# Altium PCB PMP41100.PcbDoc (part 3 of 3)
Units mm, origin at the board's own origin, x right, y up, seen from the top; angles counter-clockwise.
Board outline 49.66 x 37.36 mm, 2 copper layers (Top Layer, Bottom Layer), stack 1.016 mm thick; 100 components, 64 nets, 348 pads, 1132 vias.
Unrouted connection lines stored in the file: 60.
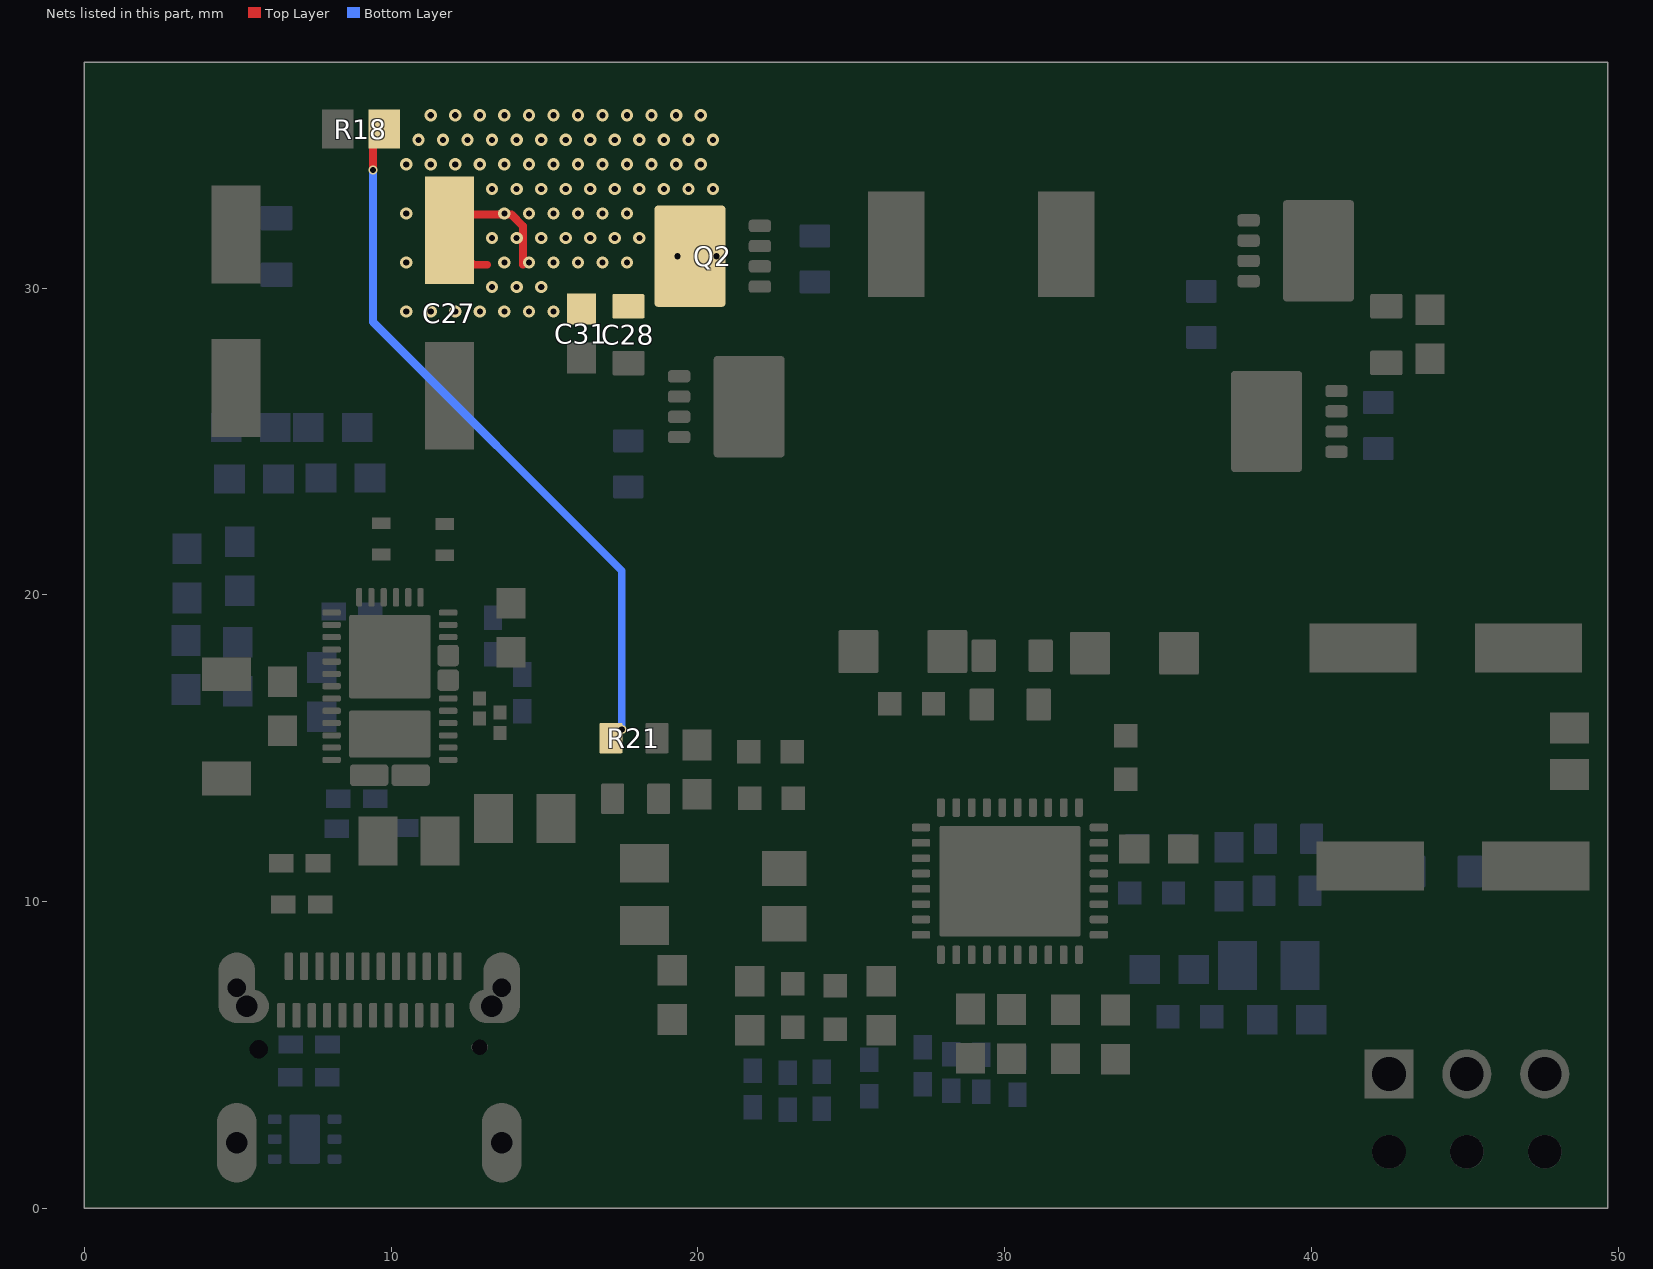
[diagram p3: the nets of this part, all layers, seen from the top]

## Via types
v1: diameter 0.4, hole 0.2, Top Layer to Bottom Layer, 988 vias
v2: diameter 0.3, hole 0.2, Top Layer to Bottom Layer, tented both sides, 103 vias
v3: diameter 0.5, hole 0.2, Top Layer to Bottom Layer, 34 vias
v4: diameter 0.4, hole 0.2, Top Layer to Bottom Layer, tented both sides, 5 vias
v5: diameter 0.4, hole 0.203, Top Layer to Bottom Layer, tented both sides, 1 vias
v6: diameter 0.61, hole 0.203, Top Layer to Bottom Layer, tented both sides, 1 vias

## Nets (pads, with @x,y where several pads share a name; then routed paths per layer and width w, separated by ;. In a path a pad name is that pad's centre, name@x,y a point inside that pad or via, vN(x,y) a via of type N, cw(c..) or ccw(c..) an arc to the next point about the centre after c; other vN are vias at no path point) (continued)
VSYS: C27.1 C28.2 C31.1 Q2.5 Q2.6 Q2.7 Q2.8 Q2.9@19.742,31.04 R18.2 R21.2 | length 29
  Top Layer w0.254: v2(9.41,33.848) 9.41,34.091 9.41,34.577 9.41,34.82 R18.2@9.774,35.185 ; C27.1@11.958,31.432 11.901,31.49 11.901,31.887 12.414,32.4 13.921,32.4 14.295,32.025 14.295,30.759 ; C27.1@12.015,31.432 12.688,30.759 13.127,30.759
  Bottom Layer w0.254: v2(9.41,33.848) 9.41,28.894 17.519,20.784 v2(17.519,15.613)
  other v1: 10.491,29.235 11.291,29.235 12.091,29.235 12.891,29.235 13.691,29.235 14.491,29.235 15.291,29.235 13.291,30.035 14.091,30.035 14.891,30.035 10.491,30.835 13.691,30.835 14.491,30.835 15.291,30.835 16.091,30.835 16.891,30.835 17.691,30.835 13.291,31.635 14.091,31.635 14.891,31.635 15.691,31.635 16.491,31.635 17.291,31.635 18.091,31.635 10.491,32.435 13.691,32.435 14.491,32.435 15.291,32.435 16.091,32.435 16.891,32.435 17.691,32.435 13.291,33.235 14.091,33.235 14.891,33.235 15.691,33.235 16.491,33.235 17.291,33.235 18.091,33.235 18.891,33.235 19.691,33.235 20.491,33.235 10.491,34.035 11.291,34.035 12.091,34.035 12.891,34.035 13.691,34.035 14.491,34.035 15.291,34.035 16.091,34.035 16.891,34.035 17.691,34.035 18.491,34.035 19.291,34.035 20.091,34.035 10.891,34.835 11.691,34.835 12.491,34.835 13.291,34.835 14.091,34.835 14.891,34.835 15.691,34.835 16.491,34.835 17.291,34.835 18.091,34.835 18.891,34.835 19.691,34.835 20.491,34.835 11.291,35.635 12.091,35.635 12.891,35.635 13.691,35.635 14.491,35.635 15.291,35.635 16.091,35.635 16.891,35.635 17.691,35.635 18.491,35.635 19.291,35.635 20.091,35.635
  other v3: 19.337,31.04 20.612,31.04
pads on no net: J1.A2 J1.A3 J1.A8 J1.A10 J1.A11 J1.ALIGN1 J1.ALIGN2 J1.B2 J1.B3 J1.B8 J1.B10 J1.B11 J2.4 J2.5 J2.6 Q1.9@39.293,29.668 Q1.9@39.293,31.218 Q1.9@39.293,32.768 Q1.9@39.878,30.648 Q1.9@39.878,31.788 Q1.9@40.028,31.218 Q2.9@19.947,31.04 Q2.9@20.097,30.47 Q2.9@20.097,31.61 Q2.9@20.682,29.49 Q2.9@20.682,31.04 Q2.9@20.682,32.59 Q3.9@38.744,25.654 Q3.9@38.894,25.084 Q3.9@38.894,26.224 Q3.9@39.479,24.104 Q3.9@39.479,25.654 Q3.9@39.479,27.204 Q4.9@20.729,24.585 Q4.9@20.729,26.135 Q4.9@20.729,27.685 Q4.9@21.314,25.565 Q4.9@21.314,26.705 Q4.9@21.464,26.135 U1.7@7.179,1.803 U1.7@7.179,2.703 U3.15 U3.16 U3.31
copper on no net: | length 1778.5
  Top Layer w0.025: 191.814,9.015 194.346,11.547 197.394,14.595 200.442,17.643 203.49,20.691 206.538,23.739 209.586,26.787 212.634,29.835 ; 191.814,10.539 192.822,11.547 195.87,14.595 198.918,17.643 201.966,20.691 205.014,23.739 208.062,26.787 211.11,29.835 ; 191.814,12.063 194.346,14.595 197.394,17.643 200.442,20.691 203.49,23.739 206.538,26.787 209.586,29.835 ; 191.814,13.587 192.822,14.595 195.87,17.643 198.918,20.691 201.966,23.739 205.014,26.787 208.062,29.835 ; 191.814,15.111 194.346,17.643 197.394,20.691 200.442,23.739 203.49,26.787 206.538,29.835 ; 191.814,16.635 192.822,17.643 195.87,20.691 198.918,23.739 201.966,26.787 205.014,29.835 ; 191.814,18.159 194.346,20.691 197.394,23.739 200.442,26.787 203.49,29.835 ; 191.814,19.683 192.822,20.691 195.87,23.739 198.918,26.787 201.966,29.835 ; 191.814,21.207 194.346,23.739 197.394,26.787 200.442,29.835 ; 191.814,22.731 192.822,23.739 195.87,26.787 198.918,29.835 ; 191.814,24.255 194.346,26.787 197.394,29.835 ; 191.814,25.779 192.822,26.787 195.87,29.835 ; 191.814,27.303 194.346,29.835 ; 191.814,28.827 192.822,29.835 ; 192.822,8.499 195.87,11.547 198.918,14.595 201.966,17.643 205.014,20.691 208.062,23.739 211.11,26.787 214.158,29.835 ; 194.346,8.499 197.394,11.547 200.442,14.595 203.49,17.643 206.538,20.691 209.586,23.739 212.634,26.787 215.682,29.835 ; 195.87,8.499 198.918,11.547 201.966,14.595 205.014,17.643 208.062,20.691 211.11,23.739 214.158,26.787 217.206,29.835 ; 197.394,8.499 200.442,11.547 203.49,14.595 206.538,17.643 209.586,20.691 212.634,23.739 215.682,26.787 218.73,29.835 ; 198.918,8.499 201.966,11.547 205.014,14.595 208.062,17.643 211.11,20.691 214.158,23.739 217.206,26.787 220.254,29.835 ; 200.442,8.499 203.49,11.547 206.538,14.595 209.586,17.643 212.634,20.691 215.682,23.739 218.73,26.787 220.254,28.311 ; 201.966,8.499 205.014,11.547 208.062,14.595 211.11,17.643 214.158,20.691 217.206,23.739 220.254,26.787 ; 203.49,8.499 206.538,11.547 209.586,14.595 212.634,17.643 215.682,20.691 218.73,23.739 220.254,25.263 ; 205.014,8.499 208.062,11.547 211.11,14.595 214.158,17.643 217.206,20.691 220.254,23.739 ; 206.538,8.499 209.586,11.547 212.634,14.595 215.682,17.643 218.73,20.691 220.254,22.215 ; 208.062,8.499 211.11,11.547 214.158,14.595 217.206,17.643 220.254,20.691 ; 209.586,8.499 212.634,11.547 215.682,14.595 218.73,17.643 220.254,19.167 ; 211.11,8.499 214.158,11.547 217.206,14.595 220.254,17.643 ; 212.634,8.499 215.682,11.547 218.73,14.595 220.254,16.119 ; 214.158,8.499 217.206,11.547 220.254,14.595 ; 215.682,8.499 218.73,11.547 220.254,13.071 ; 217.206,8.499 220.254,11.547 ; 218.73,8.499 220.254,10.023
  Top Layer w0.254: 35.142,4.853 35.142,4.878 36.796,6.533 37.209,6.533 37.38,6.704 37.38,6.891 ; 36.43,4.491 37.155,4.491 38.557,5.893 39.263,5.893 39.611,6.241 39.611,6.266
  Top Layer w0.381: 104.968,11.547 115.38,11.547 138.995,11.547 160.833,11.547 177.339,11.547 191.814,11.547 220.254,11.547 ; 104.968,14.595 115.38,14.595 138.995,14.595 160.833,14.595 177.339,14.595 191.814,14.595 220.254,14.595 ; 104.968,17.643 115.38,17.643 138.995,17.643 160.833,17.643 177.339,17.643 191.814,17.643 220.254,17.643 ; 104.968,20.691 115.38,20.691 138.995,20.691 160.833,20.691 177.339,20.691 191.814,20.691 220.254,20.691 ; 104.968,23.739 115.38,23.739 138.995,23.739 160.833,23.739 177.339,23.739 191.814,23.739 220.254,23.739 ; 104.968,26.787 115.38,26.787 138.995,26.787 160.833,26.787 177.339,26.787 191.814,26.787 220.254,26.787 ; 104.968,29.835 220.254,29.835 ; 115.38,32.883 115.38,8.499 ; 138.995,32.883 138.995,8.499 ; 160.833,32.883 160.833,8.499 ; 177.339,32.883 177.339,8.499 ; 191.814,32.883 191.814,8.499 ; 115.38,8.499 104.968,8.499 104.968,32.883 220.254,32.883 220.254,8.499 191.814,8.499 ; 115.38,8.499 138.995,8.499 ; 138.995,8.499 160.833,8.499 ; 160.833,8.499 177.339,8.499 ; 177.339,8.499 191.814,8.499

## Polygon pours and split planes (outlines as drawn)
P_OUT on Top Layer "TOP_LAYER_P_OUT_P114" (solid, remove dead copper, pour order 114): 45.771,15.557 47.665,15.549 47.664,15.107 49.251,15.098 49.251,15.557 49.251,29.722 45.771,29.722
PPHV on Top Layer "TOP_LAYER_PPHV_P111" (solid, remove dead copper, pour order 111): 0,13.27 9.884,13.27 9.911,13.298 9.911,14.383 9.861,14.433 7.183,14.433 7.009,14.607 7.009,16.213 3.581,16.213 3.581,29.774 7.845,29.774 7.845,34.462 8.817,34.51 8.809,36.711 8.344,36.711 0,36.711
BAT on Top Layer "TOP_LAYER_BAT_P115" (solid, remove dead copper, pour order 115): 45.561,-0.313 49.269,-0.313 49.269,14.688 47.673,14.694 47.673,13.85 45.561,13.852
PGND on Top Layer "TOP_LAYER_PGND_P112" (solid, remove dead copper, pour order 112): 17.021,2.146 18.344,0.823 39.088,0.823 39.088,19.175 37.976,20.286 17.021,20.286
PGND on Top Layer "TOP_LAYER_PGND_P110" (solid, remove dead copper, pour order 110): 14.439,28.533 14.439,15.718 3.751,15.718 3.751,28.533
PGND on Top Layer "TOP_LAYER_PGND_P035" (solid, pour order 35): 13.623,25.702 13.623,20.721 45.315,20.721 45.315,21.824 18.847,21.824 18.847,25.702
VBUS on Top Layer "TOP_LAYER_VBUS_P043" (solid, remove dead copper, pour order 43): 10.955,10.958 14.209,10.958 14.23,14.408 10.955,14.408
NetC1_1 on Top Layer "TOP_LAYER_NETC1_1_P008" (solid, remove dead copper, pour order 8): 7.06,3.567 7.06,12.778 11.161,12.778 11.161,3.567
PGND on Top Layer "TOP_LAYER_PGND_P040" (solid, remove dead copper, pour order 40): 16.467,0.71 16.467,21.504 14.415,21.504 14.415,9.371 11.471,9.371 11.502,3.376 6.67,3.376 6.67,0.71
SW2 on Top Layer "TOP_LAYER_SW2_P019" (solid, remove dead copper, pour order 19): 39.954,22.309 39.954,27.786 38.691,27.786 38.362,28.115 38.362,36.711 29.469,36.711 29.469,22.309
P_OUT on Top Layer "TOP_LAYER_P_OUT_P025" (solid, remove dead copper, pour order 25): 38.691,36.711 38.691,28.383 48.971,28.383 48.971,36.711
VSYS on Top Layer "TOP_LAYER_VSYS_P013" (solid, remove dead copper, pour order 13): 21.14,36.711 21.14,28.646 10.282,28.646 10.282,34.514 9.196,34.514 9.196,36.711 9.803,36.711
SW1 on Top Layer "TOP_LAYER_SW1_P018" (solid, remove dead copper, pour order 18): 19.934,28.287 19.934,22.332 28.147,22.332 28.147,36.711 21.364,36.711 21.364,28.287
PGND on Top Layer "TOP_LAYER_PGND_P026" (solid, remove dead copper, pour order 26): 39.785,0.757 45.315,0.757 45.315,28.136 39.785,28.136
PGND on Top Layer "TOP_LAYER_PGND_P007" (solid, remove dead copper, pour order 7): 0,0.34 6.996,0.34 6.996,12.778 0,12.778
PGND on Top Layer "TOP_LAYER_PGND_P032" (solid, remove dead copper, pour order 32): 13.474,28.383 13.474,20.721 19.759,20.721 19.759,28.383
DRAIN on Bottom Layer "BOTTOM_LAYER_DRAIN_P132" (solid, remove dead copper, pour order 132): 7.801,16.345 7.801,13.814 11.693,13.814 11.693,16.345 7.831,16.345
PGND on Bottom Layer "BOTTOM_LAYER_PGND_P127" (solid, remove dead copper, pour order 127): 14.89,30.753 14.89,8.707 3.77,8.707 3.77,30.753
BAT on Bottom Layer "BOTTOM_LAYER_BAT_P131" (solid, remove dead copper, pour order 131): 45.58,-0.426 49.059,-0.426 49.059,13.74 45.58,13.74
P_OUT on Bottom Layer "BOTTOM_LAYER_P_OUT_P130" (solid, remove dead copper, pour order 130): 45.79,15.557 49.269,15.557 49.269,29.609 45.79,29.609
PGND on Bottom Layer "BOTTOM_LAYER_PGND_P129" (solid, remove dead copper, pour order 129): 17.04,2.033 18.363,0.71 39.106,0.71 39.106,19.044 37.977,20.174 17.04,20.174
PPHV on Bottom Layer "BOTTOM_LAYER_PPHV_P128" (solid, remove dead copper, pour order 128): 0.019,13.158 9.771,13.158 9.93,13.316 9.93,14.271 9.88,14.321 7.201,14.321 7.028,14.494 7.028,16.101 3.6,16.101 3.6,31.04 7.864,31.04 7.864,34.349 8.835,34.398 8.827,36.598 8.363,36.598 0.019,36.598
PGND on Bottom Layer "BOTTOM_LAYER_PGND_P125" (solid, remove dead copper, pour order 125): 16.403,0.71 16.467,9.323 16.467,21.392 14.434,21.392 14.434,9.259 11.49,9.259 11.521,3.263 6.689,3.263 6.689,0.71
PGND on Bottom Layer "BOTTOM_LAYER_PGND_P124" (solid, pour order 124): 13.641,25.589 13.641,20.401 45.333,20.401 45.333,21.711 18.865,21.711 18.865,25.589
PGND on Bottom Layer "BOTTOM_LAYER_PGND_P123" (solid, remove dead copper, pour order 123): 10.841,28.271 10.841,20.9 19.778,20.9 19.778,28.271
PGND on Bottom Layer "BOTTOM_LAYER_PGND_P122" (solid, remove dead copper, pour order 122): 39.804,0.644 45.333,0.644 45.333,28.023 39.804,28.023
P_OUT on Bottom Layer "BOTTOM_LAYER_P_OUT_P121" (solid, remove dead copper, pour order 121): 38.71,36.598 38.71,28.271 48.99,28.271 48.99,36.598
SW2 on Bottom Layer "BOTTOM_LAYER_SW2_P120" (solid, remove dead copper, pour order 120): 39.973,22.196 39.973,27.673 38.71,27.673 38.381,28.003 38.381,36.598 29.469,36.598 29.469,22.196
SW1 on Bottom Layer "BOTTOM_LAYER_SW1_P119" (solid, remove dead copper, pour order 119): 19.953,28.174 19.953,22.219 28.147,22.219 28.147,36.598 21.382,36.598 21.382,28.174
VSYS on Bottom Layer "BOTTOM_LAYER_VSYS_P118" (solid, remove dead copper, pour order 118): 21.158,36.598 21.158,28.533 10.099,28.533 10.099,34.401 9.215,34.401 9.215,36.598 9.821,36.598
NetC1_1 on Bottom Layer "BOTTOM_LAYER_NETC1_1_P117" (solid, remove dead copper, pour order 117): 7.079,3.454 7.079,12.665 11.18,12.665 11.18,3.454
PGND on Bottom Layer "BOTTOM_LAYER_PGND_P116" (solid, remove dead copper, pour order 116): 0.019,0.227 7.015,0.227 7.015,12.665 0.019,12.665
NetC1_1 on Bottom Layer "BOTTOM_LAYER_NETC1_1_P000" (solid, remove dead copper, pour order 0): 6.983,1.106 10.484,1.106 10.484,5.656 6.983,5.656

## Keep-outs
Keep-Out Layer:
  text ".Layer_Name" at -9.924,-55.867 h0.3

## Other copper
Top Layer:
  text "Layer" at 106.746,30.597 h1.52
  text "Name" at 117.158,30.597 h1.52
  text "Material" at 140.773,30.597 h1.52
  text "Thickness" at 162.611,30.597 h1.52
  text "Constant" at 179.117,30.597 h1.52
  text "Board Layer Stack" at 193.592,30.597 h1.52
  text "Top Overlay" at 117.158,27.549 h1.52
  text "Top Solder" at 117.158,24.501 h1.52
  text "Solder Resist" at 140.773,24.501 h1.52
  text "0.010mm" at 162.611,24.501 h1.52
  text "3.5" at 179.117,24.501 h1.52
  text "1" at 106.746,21.453 h1.52
  text "Top Layer" at 117.158,21.453 h1.52
  text "0.036mm" at 162.611,21.453 h1.52
  text "Dielectric1" at 117.158,18.405 h1.52
  text "FR-4 High Tg" at 140.773,18.405 h1.52
  text "0.945mm" at 162.611,18.405 h1.52
  text "4.8" at 179.117,18.405 h1.52
  text "2" at 106.746,15.357 h1.52
  text "Bottom Layer" at 117.158,15.357 h1.52
  text "0.036mm" at 162.611,15.357 h1.52
  text "Bottom Solder" at 117.158,12.309 h1.52
  text "Solder Resist" at 140.773,12.309 h1.52
  text "0.010mm" at 162.611,12.309 h1.52
  text "3.5" at 179.117,12.309 h1.52
  text "Bottom Overlay" at 117.158,9.261 h1.52
  text "Total board thickness:" at 106.746,6.213 h1.52
  text "1.036mm" at 162.611,6.213 h1.52
  text ".Layer_Name" at -9.924,-55.867 h0.3
Bottom Layer:
  text ".Layer_Name" at -9.924,-55.867 h0.3

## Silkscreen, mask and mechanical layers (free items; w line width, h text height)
Top Overlay:
  text "TPS25730+BQ25756" at 40.3,35.255 h0.5
  text ".Layer_Name" at -9.924,-55.867 h0.3
Bottom Overlay:
  text ".Layer_Name" at -9.924,-55.867 h0.3
Top Paste:
  text ".Layer_Name" at -9.924,-55.867 h0.3
Bottom Paste:
  text ".Layer_Name" at -9.924,-55.867 h0.3
Top Solder:
  text ".Layer_Name" at -9.924,-55.867 h0.3
  text ".Layer_Name" at -9.924,-55.867 h0.3
Bottom Solder:
  text ".Layer_Name" at -9.924,-55.867 h0.3
Drill Guide:
  text ".Layer_Name" at -9.924,-55.867 h0.3
M1 Board Outline:
  the board outline again, w0.254
  text ".Layer_Name" at -9.924,-55.867 h0.3
M2 Board Dimensions:
  rectangle: -21.405,-44.221 -11.88,-41.046
  rectangle: -24.58,-41.046 -21.405,-37.871
  lines w0.178: -24.58,-41.046 0.82,-41.046 ; -21.405,-44.221 -21.405,-37.871 ; -18.23,-44.221 -18.23,-37.871 ; -11.88,-44.221 -11.88,-37.871 ; -5.53,-44.221 -5.53,-37.871 ; -24.58,-44.221 -24.58,-37.871 0.82,-37.871 0.82,-44.221 -24.58,-44.221
  text ".Layer_Name" at -9.924,-55.867 h0.3
M3 3D STEP Top:
  text ".Layer_Name" at -9.924,-55.867 h0.3
M4 3D STEP Bottom:
  text ".Layer_Name" at -9.924,-55.867 h0.3
Top M5 Assembly Top/M6 Assembly Bottom:
  lines w0.254: -31.996,-57.688 135.644,-57.688 ; -31.996,-52.523 135.694,-52.523 ; -31.996,-47.358 -31.996,-62.852 69.731,-62.852 135.694,-62.852 135.694,-47.358 -31.984,-47.358 -31.984,-62.852 8.034,-62.852 ; 30.615,-62.852 30.615,-47.358 ; 62.796,-52.523 62.796,-47.358 ; 84.132,-52.523 84.132,-47.358 ; 99.931,-63.017 99.931,-57.865
  text "COMPONENTS MARKED 'DNP' SHOULD NOT BE POPULATED." at 4.719,-42.151 h0.3
  text "ASSEMBLY VARIANT:" at 4.707,-45.085 h0.3
  text ".VariantName" at 31.021,-45.085 h0.3
  text "PCB VIEWED FROM TOP SIDE" at -30.383,-50.715 h0.3
  text "BOARD #:" at 32.52,-50.715 h0.3
  text ".PRJ_Number" at 46.375,-50.715 h0.3
  text "REV:" at 67.826,-50.715 h0.3
  text ".PCB_Rev" at 75.23,-50.715 h0.3
  text "SVN REV:" at 89.111,-50.715 h0.3
  text ".VersionControl_RevNumber" at 101.963,-50.715 h0.3
  text "PLOT NAME =" at -30.383,-61.096 h0.3
  text ".plot_File_Name" at -9.924,-61.096 h0.3
  text "GENERATED    :" at 32.57,-61.096 h0.3
  text ".Print_Date" at 54.656,-61.096 h0.3
  text ".Print_Time" at 73.172,-61.096 h0.3
  text "TEXAS INSTRUMENTS" at 105.291,-61.096 h0.3
Bottom M5 Assembly Top/M6 Assembly Bottom:
  lines w0.254: -32.009,-52.536 135.682,-52.536 ; -31.958,-57.7 135.682,-57.7 ; 3.754,-63.03 3.754,-57.878 ; 19.553,-52.536 19.553,-47.371 ; 40.889,-52.536 40.889,-47.371 ; 73.071,-62.865 73.071,-47.371 ; 95.651,-62.865 135.669,-62.865 135.669,-47.371 -32.009,-47.371 -32.009,-62.865 33.955,-62.865 135.682,-62.865 135.682,-47.371
  text "COMPONENTS MARKED 'DNP' SHOULD NOT BE POPULATED." at 130.411,-42.139 h0.3
  text ".VariantName" at 103.894,-45.085 h0.3
  text "ASSEMBLY VARIANT:" at 130.284,-45.085 h0.3
  text ".VersionControl_RevNumber" at 1.722,-50.728 h0.3
  text "SVN REV:" at 14.575,-50.728 h0.3
  text ".PCB_Rev" at 28.456,-50.728 h0.3
  text "REV:" at 35.86,-50.728 h0.3
  text ".PRJ_Number" at 57.31,-50.728 h0.3
  text "BOARD #:" at 71.166,-50.728 h0.3
  text "PCB VIEWED FROM BOTTOM SIDE" at 134.069,-50.728 h0.3
  text "TEXAS INSTRUMENTS" at -1.605,-61.108 h0.3
  text ".Print_Time" at 30.513,-61.108 h0.3
  text ".Print_Date" at 49.03,-61.108 h0.3
  text "GENERATED    :" at 71.115,-61.108 h0.3
  text ".plot_File_Name" at 113.609,-61.108 h0.3
  text "PLOT NAME =" at 134.069,-61.108 h0.3
M9 Title Sheet:
  drawing of 63 lines, arcs and shapes, not listed
  text "1" at 10.714,432.689 h0.3
  text "2" at 112.187,432.689 h0.3
  text "3" at 213.66,432.689 h0.3
  text "4" at 315.285,432.689 h0.3
  text "5" at 416.843,432.689 h0.3
  text "6" at 518.401,432.689 h0.3
  text "7" at 620.043,432.689 h0.3
  text "8" at 721.516,432.689 h0.3
  text "A" at -36.454,371.78 h0.3
  text "A" at 768.726,371.78 h0.3
  text "B" at -36.454,244.78 h0.3
  text "B" at 768.726,244.78 h0.3
  text "C" at -36.454,117.78 h0.3
  text "C" at 768.726,117.78 h0.3
  text "D" at -36.454,-9.22 h0.3
  text "D" at 768.726,-9.22 h0.3
  text "PROJECT TITLE:" at 690.367,-27.239 h0.3
  text ".PRJ_Title" at 691.637,-30.625 h0.3
  text "DESIGNED FOR:" at 690.367,-34.884 h0.3
  text ".PRJ_Customer" at 691.637,-38.44 h0.3
  text "FILE NAME:" at 690.367,-42.504 h0.3
  text ".PCB_File_Name_No_Path" at 691.637,-45.552 h0.3
  text "Texas Instruments (TI) and/or its licensors do not warrant the accuracy or completeness of this specification" at 564.142,-49.663 h0.3
  text "ENGINEER:" at 690.367,-49.87 h0.3
  text "LAYOUT BY:" at 728.594,-49.87 h0.3
  text "or any information contained therein. TI and/or its licensors do not warrant that this design will meet" at 562.999,-52.525 h0.3
  text ".PRJ_Engineer" at 691.637,-53.807 h0.3
  text ".PCB_Layout" at 729.877,-53.807 h0.3
  text "the specifications, will be suitable for your application or fit for any particular purpose, or will operate in" at 562.999,-55.386 h0.3
  text ".Layer_Name" at -9.924,-55.867 h0.3
  text "ALTIUM DESIGNER VERSION:" at 728.594,-57.744 h0.3
  text "an implementation. TI and/or its licensors do not warrant that the design is production worthy. You should" at 562.999,-58.248 h0.3
  text "completely validate and test your design implementation to confirm the system functionality for your application." at 564.142,-61.11 h0.3
  text ".print_Scale" at 691.637,-61.131 h0.3
  text ".Application_BuildNumber" at 729.877,-61.131 h0.3
  text "1" at 10.714,-67.564 h0.3
  text "2" at 112.187,-67.564 h0.3
  text "3" at 213.66,-67.564 h0.3
  text "4" at 315.285,-67.564 h0.3
  text "5" at 416.843,-67.564 h0.3
  text "6" at 518.401,-67.564 h0.3
  text "7" at 620.043,-67.564 h0.3
  text "8" at 721.516,-67.564 h0.3
M10 Fab Notes:
  drawing of 189 lines, arcs and shapes, not listed
  text "DESIGN INFORMATION" at 716.796,127.614 h0.3
  text "MIN. TRACK WIDTH:" at 700.424,124.258 h0.3
  text "8" at 728.269,124.258 h0.3
  text "MIL" at 732.2,124.258 h0.3
  text "MIN. CLEARANCE:" at 700.424,121.105 h0.3
  text "7.874" at 723.92,121.105 h0.3
  text "MIL" at 732.2,121.105 h0.3
  text "MIN. VIA PAD SIZE:" at 700.424,117.952 h0.3
  text "24" at 727.507,117.952 h0.3
  text "MIL" at 732.2,117.952 h0.3
  text "0.05mm (2MIL)" at 718.077,114.653 h0.3
  text "MINIMUM ANNULAR RING" at 692.062,114.444 h0.3
  text "EXTERNAL" at 736.06,114.444 h0.3
  text "PER" at 697.142,111.647 h0.3
  text "IPC-D-275 CLASS 2 LEVEL C" at 702.73,111.647 h0.3
  text "MIL, HOLES" at 740.531,109.095 h0.3
  text "+/-" at 730.562,108.877 h0.3
  text "+/-" at 752.254,108.877 h0.3
  text "REGISTRATION TOLERANCES:" at 692.062,108.85 h0.3
  text "METAL" at 722.536,108.85 h0.3
  text "5" at 737.172,108.85 h0.3
  text "3" at 758.33,108.85 h0.3
  text "MIL" at 761.283,108.85 h0.3
  text "HOLE SIZE TOLERANCE (UNLESS OTHERWISE SPECIFIED):" at 692.062,106.352 h0.3
  text "+/-" at 752.254,106.279 h0.3
  text "3" at 758.33,106.253 h0.3
  text "MIL" at 761.283,106.252 h0.3
  text "MATERIAL:" at 690.163,102.756 h0.3
  text "FR-4 High Tg" at 715.218,99.492 h0.3
  text "X" at 711.55,99.289 h0.3
  text "FR-4" at 700.856,99.174 h0.3
  text "OTHER" at 738.651,99.174 h0.3
  text "62 MIL (1.6mm) +/-10%" at 708.987,95.541 h0.3
  text "X" at 705.936,95.479 h0.3
  text "THICKNESS:" at 692.062,95.332 h0.3
  text "OTHER" at 741.623,95.332 h0.3
  text "TOLERANCE:" at 692.062,91.819 h0.3
  text "X" at 713.607,91.819 h0.3
  text "ANSI IPC-6012 TYPE 3 CLASS 2" at 718.129,91.819 h0.3
  text "OTHER +/-" at 718.128,88.157 h0.3
  text "BOW & TWIST:" at 692.062,84.469 h0.3
  text "X" at 713.607,84.469 h0.3
  text "ANSI IPC-6012 TYPE 3 CLASS 2" at 718.129,84.469 h0.3
  text "OTHER +/-" at 718.128,80.743 h0.3
  text "DRILLING:" at 690.163,77.425 h0.3
  text "NC_DRILL FILES" at 734.892,74.753 h0.3
  text "REFERENCE:" at 692.062,74.653 h0.3
  text "X" at 708.756,74.651 h0.3
  text "AS SHOWN" at 713.277,74.653 h0.3
  text "X" at 731.641,74.653 h0.3
  text "OTHER" at 742.461,71.04 h0.3
  text "PTH COPPER THICKNESS:" at 692.054,70.95 h0.3
  text "X" at 720.99,70.95 h0.3
  text "20-30 um" at 724.241,70.95 h0.3
  text "BOARD FINISH:" at 690.163,67.201 h0.3
  text "SILKSCREEN:" at 694.105,64.404 h0.3
  text "X" at 718.433,64.404 h0.3
  text "TOP" at 721.405,64.404 h0.3
  text "X" at 731.387,64.404 h0.3
  text "BOTTOM" at 734.384,64.404 h0.3
  text "SILKSCREEN COLOR:" at 694.105,60.462 h0.3
  text "X" at 718.408,60.462 h0.3
  text "WHITE" at 721.405,60.462 h0.3
  text "OTHER" at 734.384,60.462 h0.3
  text "X" at 721.735,56.819 h0.3
  text "GREEN" at 724.732,56.819 h0.3
  text "OTHER" at 740.429,56.819 h0.3
  text "SOLDER RESIST COLOR:" at 694.105,56.644 h0.3
  text "X" at 721.735,52.901 h0.3
  text "MATTE" at 724.732,52.901 h0.3
  text "SEMI-GLOSS" at 740.418,52.885 h0.3
  text "IMMERSION GOLD (ENIG)" at 717.112,48.512 h0.3
  text "ENEPIG" at 751.086,48.329 h0.3
  text "SURFACE FINISH:" at 690.163,48.304 h0.3
  text "X" at 712.591,48.304 h0.3
  text "IMM. TIN/SILVER OR EQUIV" at 698.533,44.816 h0.3
  text "OTHER" at 734.892,44.716 h0.3
  text "ARRAY/PANEL:" at 690.163,40.769 h0.3
  text "CUT AND TRIM PER M1 BOARD OUTLINE" at 717.112,40.56 h0.3
  text "N.C. ROUTE" at 717.112,37.107 h0.3
  text "X" at 734.587,37.107 h0.3
  text "V. SCORE" at 739.108,37.107 h0.3
  text "CERTIFICATION:" at 690.163,33.827 h0.3
  text "MATERIALS AND WORKMANSHIP FOR ALL PCBS" at 708.578,33.827 h0.3
  text "TO MEET OR EXCEED THE REQUIREMENTS OF:" at 708.578,31.438 h0.3
  text "X" at 699.37,28.171 h0.3
  text "ANSI IPC-A-600F CLASS ->" at 702.621,28.171 h0.3
  text "X" at 744.481,28.171 h0.3
  text "2" at 747.275,28.171 h0.3
  text "1" at 739.274,28.133 h0.3
  text "3" at 756.266,28.133 h0.3
  text "X" at 719.995,24.419 h0.3
  text "RoHS" at 723.246,24.419 h0.3
  text "OTHER" at 739.614,24.419 h0.3
  text "PER ORDER" at 749.699,24.419 h0.3
  text "ALL BOARDS MUST MEET OR EXCEED UL94-V0 REQUIREMENTS." at 690.862,20.512 h0.3
  text "PCB MUST BEAR THE UL94V-0 UL REGISTERED MATERIAL ID NUMBER" at 690.862,17.564 h0.3
  text "ADDITIONAL REQUIREMENTS:" at 690.163,13.261 h0.3
  text "MICROSECTION:" at 692.062,10.54 h0.3
  text "YES" at 715.067,10.54 h0.3
  text "REQUIRED" at 736.949,6.874 h0.3
  text "BARE BOARD ELEC. TEST:" at 692.062,6.801 h0.3
  text "NONE" at 725.227,6.801 h0.3
  text "X" at 733.952,6.801 h0.3
  text "PER ORDER" at 751.986,6.801 h0.3
  text "XX MIL VIAS REQUIRE NON-CONDUCTIVE FILL AND PLANARIZE" at 696.333,1.596 h0.3
  text "XX MIL VIAS REQUIRE CONDUCTIVE FILL AND PLANARIZE" at 696.536,-1.045 h0.3
  text "OUTER XX MIL TRACES REQUIRE 50 OHM SINGLE-ENDED IMPEDANCE" at 696.511,-5.195 h0.3
  text "LAYER 2 & 3 (INNER LAYERS) XX MIL WIDE, XX MIL SPACE / TRACES REQUIRE 100 OHM DIFFERENTIAL IMPEDANCE" at 696.308,-11.182 h0.3
  text ".Layer_Name" at -9.924,-55.867 h0.3
M11 Gerber Information:
  lines w0.254: -31.996,-57.688 135.644,-57.688 ; -31.996,-52.523 135.694,-52.523 ; -31.996,-47.358 -31.996,-62.852 69.731,-62.852 135.694,-62.852 135.694,-47.358 -31.984,-47.358 -31.984,-62.852 8.034,-62.852 ; 30.615,-62.852 30.615,-47.358 ; 62.796,-52.523 62.796,-47.358 ; 84.132,-52.523 84.132,-47.358 ; 99.931,-63.017 99.931,-57.865
  text "ALL ARTWORK VIEWED FROM TOP SIDE" at -30.383,-50.715 h0.3
  text "BOARD #:" at 32.52,-50.715 h0.3
  text ".PRJ_Number" at 46.375,-50.715 h0.3
  text "REV:" at 67.826,-50.715 h0.3
  text ".PCB_Rev" at 75.23,-50.715 h0.3
  text "SVN REV:" at 89.111,-50.715 h0.3
  text ".VersionControl_RevNumber" at 101.963,-50.715 h0.3
  text "LAYER NAME =" at -30.383,-55.867 h0.3
  text "PLOT NAME =" at -30.383,-61.096 h0.3
  text ".plot_File_Name" at -9.924,-61.096 h0.3
  text "GENERATED    :" at 32.57,-61.096 h0.3
  text ".Print_Date" at 54.656,-61.096 h0.3
  text ".Print_Time" at 73.172,-61.096 h0.3
  text "TEXAS INSTRUMENTS" at 105.291,-61.096 h0.3
M12 Stackup:
  drawing of 205 lines, arcs and shapes, not listed
  text "Layer" at 648.665,425.298 h0.3
  text "Name" at 651.122,425.298 h0.3
  text "Material" at 656.179,425.298 h0.3
  text "Thickness" at 660.886,425.298 h0.3
  text "Constant" at 664.543,425.298 h0.3
  text "Board Layer Stack" at 667.801,425.298 h0.3
  text "Top Overlay" at 651.122,424.698 h0.3
  text "Top Solder" at 651.122,424.098 h0.3
  text "Solder Resist" at 656.179,424.098 h0.3
  text "0.40mil" at 660.886,424.098 h0.3
  text "3.5" at 664.543,424.098 h0.3
  text "1" at 648.665,423.498 h0.3
  text "Top Layer" at 651.122,423.498 h0.3
  text "1.40mil" at 660.886,423.498 h0.3
  text "Dielectric1" at 651.122,422.898 h0.3
  text "FR-4 High Tg" at 656.179,422.898 h0.3
  text "37.20mil" at 660.886,422.898 h0.3
  text "4.8" at 664.543,422.898 h0.3
  text "2" at 648.665,422.298 h0.3
  text "Bottom Layer" at 651.122,422.298 h0.3
  text "1.40mil" at 660.886,422.298 h0.3
  text "Bottom Solder" at 651.122,421.698 h0.3
  text "Solder Resist" at 656.179,421.698 h0.3
  text "0.40mil" at 660.886,421.698 h0.3
  text "3.5" at 664.543,421.698 h0.3
  text "Bottom Overlay" at 651.122,421.098 h0.3
  text ".Layer_Name" at -9.924,-55.867 h0.3
M13 Component Bodies Top:
  text ".Layer_Name" at -9.924,-55.867 h0.3
M14 Component Bodies Bottom:
  text ".Layer_Name" at -9.924,-55.867 h0.3
M15 Courtyards Top:
  text ".Layer_Name" at -9.924,-55.867 h0.3
M16 Courtyards Bottom:
  text ".Layer_Name" at -9.924,-55.867 h0.3
Drill Drawing:
  circle w0.254: c3.676,81.121 r0.702
  circle w0.254: c3.676,77.963 r0.421
  circle w0.254: c3.676,77.963 r0.702
  lines w0.254: 2.974,83.577 2.974,83.928 3.325,84.279 2.974,84.63 2.974,84.98 3.325,84.98 3.676,84.63 4.027,84.98 4.378,84.98 4.378,84.63 4.027,84.279 4.378,83.928 4.378,83.577 4.027,83.577 3.676,83.928 3.325,83.577 2.974,83.577 ; 2.974,87.086 3.325,87.086 3.676,86.735 4.027,87.086 4.378,87.086 4.027,87.436 4.378,87.787 4.027,87.787 3.676,88.138 3.325,87.787 2.974,87.787 3.325,87.436 2.974,87.086 ; 2.974,91.296 4.378,91.296 3.676,89.892 2.974,91.296 ; 2.974,93.05 3.676,93.401 4.378,93.05 4.027,93.752 4.378,94.454 3.676,94.103 2.974,94.454 3.325,93.752 2.974,93.05 ; 2.974,96.559 3.325,96.559 3.325,96.208 4.027,96.208 4.027,96.559 4.378,96.559 4.378,97.261 4.027,97.261 4.027,97.611 3.325,97.611 3.325,97.261 2.974,97.261 2.974,96.559 ; 2.974,99.366 4.378,99.366 4.378,100.769 2.974,100.769 2.974,99.366 ; 2.974,103.225 3.676,102.523 4.378,103.225 3.676,103.927 2.974,103.225
  lines w0.305: 1.702,76.314 81.818,76.314 ; 1.702,104.734 81.818,104.734 ; 10.283,73.157 10.283,107.892 ; 18.647,73.157 18.647,107.892 ; 32.922,73.157 32.922,107.892 ; 39.504,73.157 39.504,107.892 ; 49.033,73.157 49.033,107.892 ; 67.431,73.157 67.431,107.892 ; 1.702,73.157 81.818,73.157 81.818,107.892 1.702,107.892 1.702,73.157
  text "Symbol" at 3.596,105.681 h1.83
  text "Count" at 11.231,105.681 h1.83
  text "Hole Size" at 19.595,105.681 h1.83
  text "Plated" at 33.869,105.681 h1.83
  text "Hole Type" at 40.451,105.681 h1.83
  text "Drill Layer Pair" at 49.98,105.681 h1.83
  text "Hole Tolerance" at 68.378,105.681 h1.83
  text "1130" at 11.231,102.523 h1.52
  text "0.200mm (7.87mil)" at 19.595,102.523 h1.52
  text "PTH" at 33.869,102.523 h1.52
  text "Round" at 40.451,102.523 h1.52
  text "Top Layer - Bottom Layer" at 49.98,102.523 h1.52
  text "2" at 11.231,99.366 h1.52
  text "0.203mm (8.00mil)" at 19.595,99.366 h1.52
  text "PTH" at 33.869,99.366 h1.52
  text "Round" at 40.451,99.366 h1.52
  text "Top Layer - Bottom Layer" at 49.98,99.366 h1.52
  text "1" at 11.231,96.208 h1.52
  text "0.500mm (19.69mil)" at 19.595,96.208 h1.52
  text "NPTH" at 33.869,96.208 h1.52
  text "Slot" at 40.451,96.208 h1.52
  text "Top Layer - Bottom Layer" at 49.98,96.208 h1.52
  text "+/-0.030mm" at 68.378,96.208 h1.52
  text "1" at 11.231,93.05 h1.52
  text "0.600mm (23.62mil)" at 19.595,93.05 h1.52
  text "NPTH" at 33.869,93.05 h1.52
  text "Round" at 40.451,93.05 h1.52
  text "Top Layer - Bottom Layer" at 49.98,93.05 h1.52
  text "+/-0.030mm" at 68.378,93.05 h1.52
  text "2" at 11.231,89.892 h1.52
  text "0.600mm (23.62mil)" at 19.595,89.892 h1.52
  text "PTH" at 33.869,89.892 h1.52
  text "Slot" at 40.451,89.892 h1.52
  text "Top Layer - Bottom Layer" at 49.98,89.892 h1.52
  text "+/-0.050mm" at 68.378,89.892 h1.52
  text "2" at 11.231,86.735 h1.52
  text "0.700mm (27.56mil)" at 19.595,86.735 h1.52
  text "PTH" at 33.869,86.735 h1.52
  text "Slot" at 40.451,86.735 h1.52
  text "Top Layer - Bottom Layer" at 49.98,86.735 h1.52
  text "+/-0.050mm" at 68.378,86.735 h1.52
  text "2" at 11.231,83.577 h1.52
  text "0.700mm (27.56mil)" at 19.595,83.577 h1.52
  text "PTH" at 33.869,83.577 h1.52
  text "Slot" at 40.451,83.577 h1.52
  text "Top Layer - Bottom Layer" at 49.98,83.577 h1.52
  text "+/-0.050mm" at 68.378,83.577 h1.52
  text "3" at 11.231,80.419 h1.52
  text "1.100mm (43.31mil)" at 19.595,80.419 h1.52
  text "NPTH" at 33.869,80.419 h1.52
  text "Round" at 40.451,80.419 h1.52
  text "Top Layer - Bottom Layer" at 49.98,80.419 h1.52
  text "3" at 11.231,77.262 h1.52
  text "1.100mm (43.31mil)" at 19.595,77.262 h1.52
  text "PTH" at 33.869,77.262 h1.52
  text "Round" at 40.451,77.262 h1.52
  text "Top Layer - Bottom Layer" at 49.98,77.262 h1.52
  text "1146 Total" at 11.231,74.104 h1.52
  text "Slot definitions :" at 3.596,71.893 h1.52
  text "Routed Path Length" at 15.045,71.893 h1.52
  text "= Calculated from tool start centre position to tool end centre position." at 28.754,71.893 h1.52
  text "Hole Length" at 15.045,70.63 h1.52
  text "= Routed Path Length + Tool Size = Slot length as defined in the PCB layout" at 23.679,70.63 h1.52
  text ".Layer_Name" at -9.924,-55.867 h0.3
M17 Embedded Cavity:
  text ".Layer_Name" at -9.924,-55.867 h0.3
M18 Embedded Assembly:
  text ".Layer_Name" at -9.924,-55.867 h0.3
M19 Embedded Keepout:
  text ".Layer_Name" at -9.67,-55.613 h0.3

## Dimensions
0,0 to 0,37.358 on M2 Board Dimensions
0,0 to 49.657,0 on M2 Board Dimensions
-24.58,-44.221 to 0.82,-44.221 on M2 Board Dimensions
